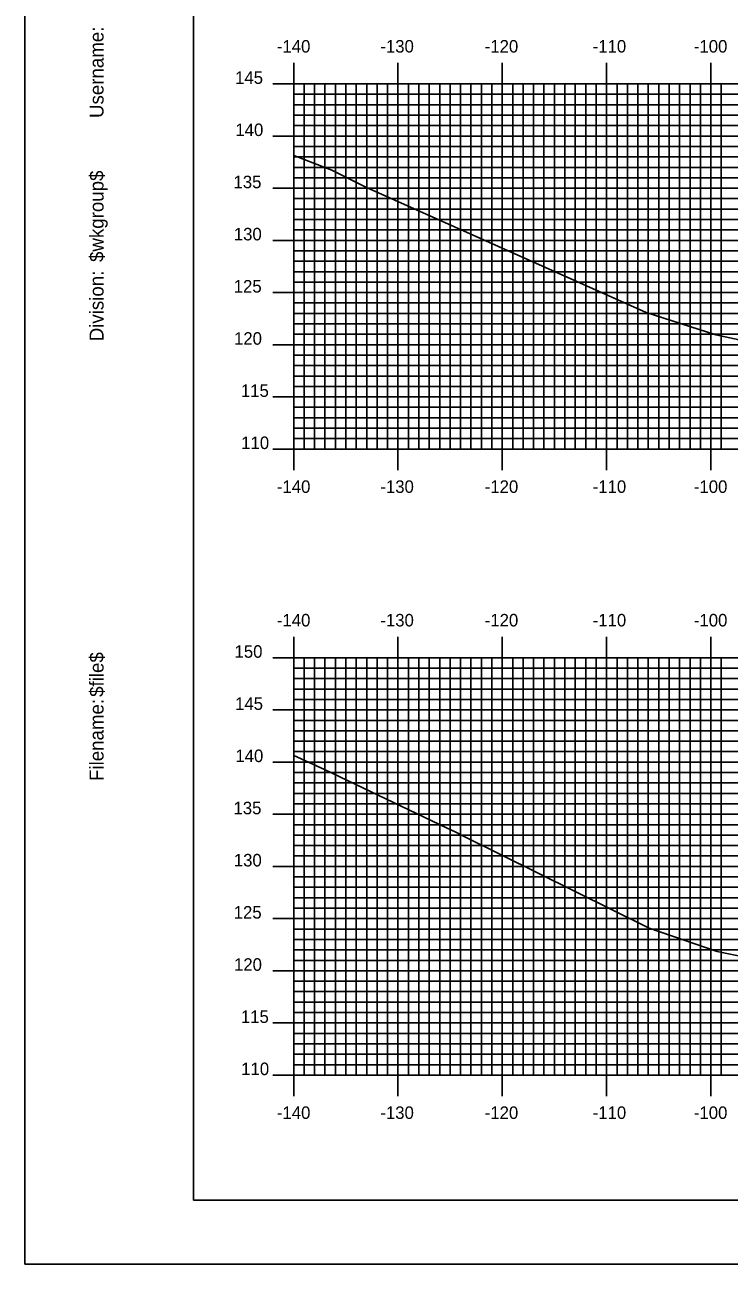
# Model space of a CAD drawing. Extents: x 853107 to 853450, y 366605 to 366825.
# Drawn here: x 853106.7 to 853174.3, y 366604.9 to 366723.7 of the extents above; entities that cross this region are included whole.
import ezdxf

# ---------------------------------------------------------------- set-up
doc = ezdxf.new("R2010")
doc.units = 0
for name, color, linetype in [('BORDER', 7, 'Continuous'), ('H_V ANNOTATION', 7, 'Continuous'), ('MAJOR', 7, 'Continuous'), ('MINOR', 7, 'Continuous'), ('PLOT BOUNDARY', 7, 'Continuous'), ('S_Roadway_Centerline', 7, 'Continuous')]:
    doc.layers.add(name, color=color, linetype=linetype)

msp = doc.modelspace()

# ---------------------------------------------------------------- linework, layer by layer
at = {"layer": 'BORDER'}
msp.add_lwpolyline([(853122.9, 366611.06), (853442.9, 366611.06), (853442.9, 366821.06), (853122.9, 366821.06)], close=True, dxfattribs=at)
at = {"layer": 'MAJOR'}
for p, q in [((853132.5, 366720.06), (853132.5, 366718.06)), ((853142.5, 366720.06), (853142.5, 366718.06)), ((853152.5, 366720.06), (853152.5, 366718.06)), ((853162.5, 366720.06), (853162.5, 366718.06)), ((853172.5, 366720.06), (853172.5, 366718.06)), ((853130.5, 366718.06), (853132.5, 366718.06)), ((853132.5, 366718.06), (853412.5, 366718.06)), ((853132.5, 366683.06), (853132.5, 366718.06)), ((853132.5, 366683.06), (853132.5, 366718.06)), ((853132.5, 366718.06), (853412.5, 366718.06)), ((853142.5, 366683.06), (853142.5, 366718.06)), ((853152.5, 366683.06), (853152.5, 366718.06)), ((853162.5, 366683.06), (853162.5, 366718.06)), ((853172.5, 366683.06), (853172.5, 366718.06)), ((853130.5, 366713.06), (853132.5, 366713.06)), ((853132.5, 366713.06), (853412.5, 366713.06)), ((853130.5, 366708.06), (853132.5, 366708.06)), ((853132.5, 366708.06), (853412.5, 366708.06)), ((853130.5, 366703.06), (853132.5, 366703.06)), ((853132.5, 366703.06), (853412.5, 366703.06)), ((853130.5, 366698.06), (853132.5, 366698.06)), ((853132.5, 366698.06), (853412.5, 366698.06)), ((853130.5, 366693.06), (853132.5, 366693.06)), ((853132.5, 366693.06), (853412.5, 366693.06)), ((853130.5, 366688.06), (853132.5, 366688.06)), ((853132.5, 366688.06), (853412.5, 366688.06)), ((853130.5, 366683.06), (853132.5, 366683.06)), ((853132.5, 366683.06), (853412.5, 366683.06)), ((853132.5, 366683.06), (853412.5, 366683.06)), ((853132.5, 366681.05), (853132.5, 366683.06)), ((853142.5, 366681.05), (853142.5, 366683.06)), ((853152.5, 366681.05), (853152.5, 366683.06)), ((853162.5, 366681.05), (853162.5, 366683.06)), ((853172.5, 366681.05), (853172.5, 366683.06)), ((853132.5, 366665.06), (853132.5, 366663.06)), ((853142.5, 366665.06), (853142.5, 366663.06)), ((853152.5, 366665.06), (853152.5, 366663.06)), ((853162.5, 366665.06), (853162.5, 366663.06)), ((853172.5, 366665.06), (853172.5, 366663.06)), ((853130.5, 366663.06), (853132.5, 366663.06)), ((853132.5, 366663.06), (853412.5, 366663.06)), ((853132.5, 366623.06), (853132.5, 366663.06)), ((853132.5, 366623.06), (853132.5, 366663.06)), ((853132.5, 366663.06), (853412.5, 366663.06)), ((853142.5, 366623.06), (853142.5, 366663.06)), ((853152.5, 366623.06), (853152.5, 366663.06)), ((853162.5, 366623.06), (853162.5, 366663.06)), ((853172.5, 366623.06), (853172.5, 366663.06)), ((853130.5, 366658.06), (853132.5, 366658.06)), ((853132.5, 366658.06), (853412.5, 366658.06)), ((853130.5, 366653.06), (853132.5, 366653.06)), ((853132.5, 366653.06), (853412.5, 366653.06)), ((853130.5, 366648.06), (853132.5, 366648.06)), ((853132.5, 366648.06), (853412.5, 366648.06)), ((853130.5, 366643.06), (853132.5, 366643.06)), ((853132.5, 366643.06), (853412.5, 366643.06)), ((853130.5, 366638.06), (853132.5, 366638.06)), ((853132.5, 366638.06), (853412.5, 366638.06)), ((853130.5, 366633.06), (853132.5, 366633.06)), ((853132.5, 366633.06), (853412.5, 366633.06)), ((853130.5, 366628.06), (853132.5, 366628.06)), ((853132.5, 366628.06), (853412.5, 366628.06)), ((853130.5, 366623.06), (853132.5, 366623.06)), ((853132.5, 366623.06), (853412.5, 366623.06)), ((853132.5, 366623.06), (853412.5, 366623.06)), ((853132.5, 366621.05), (853132.5, 366623.06)), ((853142.5, 366621.05), (853142.5, 366623.06)), ((853152.5, 366621.05), (853152.5, 366623.06)), ((853162.5, 366621.05), (853162.5, 366623.06)), ((853172.5, 366621.05), (853172.5, 366623.06))]:
    msp.add_line(p, q, dxfattribs=at)
at = {"layer": 'MINOR'}
for p, q in [((853133.5, 366683.06), (853133.5, 366718.06)), ((853134.5, 366683.06), (853134.5, 366718.06)), ((853135.5, 366683.06), (853135.5, 366718.06)), ((853136.5, 366683.06), (853136.5, 366718.06)), ((853137.5, 366683.06), (853137.5, 366718.06)), ((853138.5, 366683.06), (853138.5, 366718.06)), ((853139.5, 366683.06), (853139.5, 366718.06)), ((853140.5, 366683.06), (853140.5, 366718.06)), ((853141.5, 366683.06), (853141.5, 366718.06)), ((853143.5, 366683.06), (853143.5, 366718.06)), ((853144.5, 366683.06), (853144.5, 366718.06)), ((853145.5, 366683.06), (853145.5, 366718.06)), ((853146.5, 366683.06), (853146.5, 366718.06)), ((853147.5, 366683.06), (853147.5, 366718.06)), ((853148.5, 366683.06), (853148.5, 366718.06)), ((853149.5, 366683.06), (853149.5, 366718.06)), ((853150.5, 366683.06), (853150.5, 366718.06)), ((853151.5, 366683.06), (853151.5, 366718.06)), ((853153.5, 366683.06), (853153.5, 366718.06)), ((853154.5, 366683.06), (853154.5, 366718.06)), ((853155.5, 366683.06), (853155.5, 366718.06)), ((853156.5, 366683.06), (853156.5, 366718.06)), ((853157.5, 366683.06), (853157.5, 366718.06)), ((853158.5, 366683.06), (853158.5, 366718.06)), ((853159.5, 366683.06), (853159.5, 366718.06)), ((853160.5, 366683.06), (853160.5, 366718.06)), ((853161.5, 366683.06), (853161.5, 366718.06)), ((853163.5, 366683.06), (853163.5, 366718.06)), ((853164.5, 366683.06), (853164.5, 366718.06)), ((853165.5, 366683.06), (853165.5, 366718.06)), ((853166.5, 366683.06), (853166.5, 366718.06)), ((853167.5, 366683.06), (853167.5, 366718.06)), ((853168.5, 366683.06), (853168.5, 366718.06)), ((853169.5, 366683.06), (853169.5, 366718.06)), ((853170.5, 366683.06), (853170.5, 366718.06)), ((853171.5, 366683.06), (853171.5, 366718.06)), ((853173.5, 366683.06), (853173.5, 366718.06)), ((853132.5, 366717.06), (853412.5, 366717.06)), ((853132.5, 366717.06), (853134.51, 366717.06)), ((853132.5, 366716.06), (853412.5, 366716.06)), ((853132.5, 366716.06), (853134.51, 366716.06)), ((853132.5, 366715.06), (853412.5, 366715.06)), ((853132.5, 366715.06), (853134.51, 366715.06)), ((853132.5, 366714.06), (853412.5, 366714.06)), ((853132.5, 366714.06), (853134.51, 366714.06)), ((853132.5, 366712.06), (853412.5, 366712.06)), ((853132.5, 366712.06), (853134.51, 366712.06)), ((853132.5, 366711.06), (853412.5, 366711.06)), ((853132.5, 366711.06), (853134.51, 366711.06)), ((853132.5, 366710.06), (853412.5, 366710.06)), ((853132.5, 366710.06), (853134.51, 366710.06)), ((853132.5, 366709.06), (853412.5, 366709.06)), ((853132.5, 366709.06), (853134.51, 366709.06)), ((853132.5, 366707.06), (853412.5, 366707.06)), ((853132.5, 366707.06), (853134.51, 366707.06)), ((853132.5, 366706.06), (853412.5, 366706.06)), ((853132.5, 366706.06), (853134.51, 366706.06)), ((853132.5, 366705.06), (853412.5, 366705.06)), ((853132.5, 366705.06), (853134.51, 366705.06)), ((853132.5, 366704.06), (853412.5, 366704.06)), ((853132.5, 366704.06), (853134.51, 366704.06)), ((853132.5, 366702.06), (853412.5, 366702.06)), ((853132.5, 366702.06), (853134.51, 366702.06)), ((853132.5, 366701.06), (853412.5, 366701.06)), ((853132.5, 366701.06), (853134.51, 366701.06)), ((853132.5, 366700.06), (853412.5, 366700.06)), ((853132.5, 366700.06), (853134.51, 366700.06)), ((853132.5, 366699.06), (853412.5, 366699.06)), ((853132.5, 366699.06), (853134.51, 366699.06)), ((853132.5, 366697.06), (853412.5, 366697.06)), ((853132.5, 366697.06), (853134.51, 366697.06)), ((853132.5, 366696.06), (853412.5, 366696.06)), ((853132.5, 366696.06), (853134.51, 366696.06)), ((853132.5, 366695.06), (853412.5, 366695.06)), ((853132.5, 366695.06), (853134.51, 366695.06)), ((853132.5, 366694.06), (853412.5, 366694.06)), ((853132.5, 366694.06), (853134.51, 366694.06)), ((853132.5, 366692.06), (853412.5, 366692.06)), ((853132.5, 366692.06), (853134.51, 366692.06)), ((853132.5, 366691.06), (853412.5, 366691.06)), ((853132.5, 366691.06), (853134.51, 366691.06)), ((853132.5, 366690.06), (853412.5, 366690.06)), ((853132.5, 366690.06), (853134.51, 366690.06)), ((853132.5, 366689.06), (853412.5, 366689.06)), ((853132.5, 366689.06), (853134.51, 366689.06)), ((853132.5, 366687.06), (853412.5, 366687.06)), ((853132.5, 366687.06), (853134.51, 366687.06)), ((853132.5, 366686.06), (853412.5, 366686.06)), ((853132.5, 366686.06), (853134.51, 366686.06)), ((853132.5, 366685.06), (853412.5, 366685.06)), ((853132.5, 366685.06), (853134.51, 366685.06)), ((853132.5, 366684.06), (853412.5, 366684.06)), ((853132.5, 366684.06), (853134.51, 366684.06)), ((853133.5, 366623.06), (853133.5, 366663.06)), ((853134.5, 366623.06), (853134.5, 366663.06)), ((853135.5, 366623.06), (853135.5, 366663.06)), ((853136.5, 366623.06), (853136.5, 366663.06)), ((853137.5, 366623.06), (853137.5, 366663.06)), ((853138.5, 366623.06), (853138.5, 366663.06)), ((853139.5, 366623.06), (853139.5, 366663.06)), ((853140.5, 366623.06), (853140.5, 366663.06)), ((853141.5, 366623.06), (853141.5, 366663.06)), ((853143.5, 366623.06), (853143.5, 366663.06)), ((853144.5, 366623.06), (853144.5, 366663.06)), ((853145.5, 366623.06), (853145.5, 366663.06)), ((853146.5, 366623.06), (853146.5, 366663.06)), ((853147.5, 366623.06), (853147.5, 366663.06)), ((853148.5, 366623.06), (853148.5, 366663.06)), ((853149.5, 366623.06), (853149.5, 366663.06)), ((853150.5, 366623.06), (853150.5, 366663.06)), ((853151.5, 366623.06), (853151.5, 366663.06)), ((853153.5, 366623.06), (853153.5, 366663.06)), ((853154.5, 366623.06), (853154.5, 366663.06)), ((853155.5, 366623.06), (853155.5, 366663.06)), ((853156.5, 366623.06), (853156.5, 366663.06)), ((853157.5, 366623.06), (853157.5, 366663.06)), ((853158.5, 366623.06), (853158.5, 366663.06)), ((853159.5, 366623.06), (853159.5, 366663.06)), ((853160.5, 366623.06), (853160.5, 366663.06)), ((853161.5, 366623.06), (853161.5, 366663.06)), ((853163.5, 366623.06), (853163.5, 366663.06)), ((853164.5, 366623.06), (853164.5, 366663.06)), ((853165.5, 366623.06), (853165.5, 366663.06)), ((853166.5, 366623.06), (853166.5, 366663.06)), ((853167.5, 366623.06), (853167.5, 366663.06)), ((853168.5, 366623.06), (853168.5, 366663.06)), ((853169.5, 366623.06), (853169.5, 366663.06)), ((853170.5, 366623.06), (853170.5, 366663.06)), ((853171.5, 366623.06), (853171.5, 366663.06)), ((853173.5, 366623.06), (853173.5, 366663.06)), ((853132.5, 366662.06), (853412.5, 366662.06)), ((853132.5, 366662.06), (853134.51, 366662.06)), ((853132.5, 366661.06), (853412.5, 366661.06)), ((853132.5, 366661.06), (853134.51, 366661.06)), ((853132.5, 366660.06), (853412.5, 366660.06)), ((853132.5, 366660.06), (853134.51, 366660.06)), ((853132.5, 366659.06), (853412.5, 366659.06)), ((853132.5, 366659.06), (853134.51, 366659.06)), ((853132.5, 366657.06), (853412.5, 366657.06)), ((853132.5, 366657.06), (853134.51, 366657.06)), ((853132.5, 366656.06), (853412.5, 366656.06)), ((853132.5, 366656.06), (853134.51, 366656.06)), ((853132.5, 366655.06), (853412.5, 366655.06)), ((853132.5, 366655.06), (853134.51, 366655.06)), ((853132.5, 366654.06), (853412.5, 366654.06)), ((853132.5, 366654.06), (853134.51, 366654.06)), ((853132.5, 366652.06), (853412.5, 366652.06)), ((853132.5, 366652.06), (853134.51, 366652.06)), ((853132.5, 366651.06), (853412.5, 366651.06)), ((853132.5, 366651.06), (853134.51, 366651.06)), ((853132.5, 366650.06), (853412.5, 366650.06)), ((853132.5, 366650.06), (853134.51, 366650.06)), ((853132.5, 366649.06), (853412.5, 366649.06)), ((853132.5, 366649.06), (853134.51, 366649.06)), ((853132.5, 366647.06), (853412.5, 366647.06)), ((853132.5, 366647.06), (853134.51, 366647.06)), ((853132.5, 366646.06), (853412.5, 366646.06)), ((853132.5, 366646.06), (853134.51, 366646.06)), ((853132.5, 366645.06), (853412.5, 366645.06)), ((853132.5, 366645.06), (853134.51, 366645.06)), ((853132.5, 366644.06), (853412.5, 366644.06)), ((853132.5, 366644.06), (853134.51, 366644.06)), ((853132.5, 366642.06), (853412.5, 366642.06)), ((853132.5, 366642.06), (853134.51, 366642.06)), ((853132.5, 366641.06), (853412.5, 366641.06)), ((853132.5, 366641.06), (853134.51, 366641.06)), ((853132.5, 366640.06), (853412.5, 366640.06)), ((853132.5, 366640.06), (853134.51, 366640.06)), ((853132.5, 366639.06), (853412.5, 366639.06)), ((853132.5, 366639.06), (853134.51, 366639.06)), ((853132.5, 366637.06), (853412.5, 366637.06)), ((853132.5, 366637.06), (853134.51, 366637.06)), ((853132.5, 366636.06), (853412.5, 366636.06)), ((853132.5, 366636.06), (853134.51, 366636.06)), ((853132.5, 366635.06), (853412.5, 366635.06)), ((853132.5, 366635.06), (853134.51, 366635.06)), ((853132.5, 366634.06), (853412.5, 366634.06)), ((853132.5, 366634.06), (853134.51, 366634.06)), ((853132.5, 366632.06), (853412.5, 366632.06)), ((853132.5, 366632.06), (853134.51, 366632.06)), ((853132.5, 366631.06), (853412.5, 366631.06)), ((853132.5, 366631.06), (853134.51, 366631.06)), ((853132.5, 366630.06), (853412.5, 366630.06)), ((853132.5, 366630.06), (853134.51, 366630.06)), ((853132.5, 366629.06), (853412.5, 366629.06)), ((853132.5, 366629.06), (853134.51, 366629.06)), ((853132.5, 366627.06), (853412.5, 366627.06)), ((853132.5, 366627.06), (853134.51, 366627.06)), ((853132.5, 366626.06), (853412.5, 366626.06)), ((853132.5, 366626.06), (853134.51, 366626.06)), ((853132.5, 366625.06), (853412.5, 366625.06)), ((853132.5, 366625.06), (853134.51, 366625.06)), ((853132.5, 366624.06), (853412.5, 366624.06)), ((853132.5, 366624.06), (853134.51, 366624.06))]:
    msp.add_line(p, q, dxfattribs=at)
at = {"layer": 'PLOT BOUNDARY'}
msp.add_lwpolyline([(853106.72, 366604.94), (853446.72, 366604.94), (853446.72, 366824.94), (853106.72, 366824.94)], close=True, dxfattribs=at)
at = {"layer": 'S_Roadway_Centerline'}
for points in [[(853132.5, 366711.19), (853136.15, 366709.79), (853139.47, 366708.14), (853166.29, 366696.15), (853172.98, 366694.01), (853177.28, 366693.08), (853179.23, 366692.99), (853189.7, 366695.2), (853194.1, 366696.11), (853200.88, 366696.93), (853201.43, 366696.92), (853210.25, 366697.23), (853213.84, 366697.36), (853216.32, 366697.44), (853216.51, 366697.43), (853219.19, 366697.5), (853223.14, 366697.57), (853228.77, 366697.71), (853232.64, 366697.78), (853240.8, 366697.96)], [(853132.5, 366653.68), (853135.46, 366652.34), (853147.22, 366646.73), (853147.98, 366646.36), (853148.84, 366645.94), (853166.58, 366637.15), (853173.1, 366634.9), (853180.75, 366633.34), (853182.02, 366633.1), (853183.71, 366633.28), (853193.39, 366635.16), (853200.79, 366636.45), (853204.64, 366636.88), (853205.13, 366636.82), (853210.17, 366637.08), (853219.65, 366637.54), (853220.08, 366637.56), (853220.74, 366637.58), (853223.92, 366637.67), (853230.24, 366637.86), (853241.74, 366638.1)]]:
    msp.add_lwpolyline(points, dxfattribs=at)

# ---------------------------------------------------------------- texts
at = {"layer": 'BORDER'}
for s, p in [('Username:', (853114.27, 366714.79)), ('$wkgroup$', (853114.27, 366700.99)), ('Division:', (853114.27, 366693.39)), ('$file$', (853114.27, 366659.31)), ('Filename:', (853114.27, 366651.25))]:
    msp.add_text(s, height=1.339, rotation=90, dxfattribs=at).set_placement(p)
at = {"layer": 'H_V ANNOTATION'}
for s, p in [('-140', (853130.89, 366721.06)), ('-130', (853140.81, 366721.06)), ('-120', (853150.82, 366721.06)), ('-110', (853161.17, 366721.06)), ('-100', (853170.87, 366721.06)), ('145', (853126.88, 366718.06)), ('140', (853126.91, 366713.06)), ('135', (853126.73, 366708.06)), ('130', (853126.76, 366703.06)), ('125', (853126.75, 366698.06)), ('120', (853126.78, 366693.06)), ('115', (853127.44, 366688.06)), ('110', (853127.47, 366683.06)), ('-140', (853130.89, 366678.86)), ('-130', (853140.81, 366678.86)), ('-120', (853150.82, 366678.86)), ('-110', (853161.17, 366678.86)), ('-100', (853170.87, 366678.86)), ('-140', (853130.89, 366666.06)), ('-130', (853140.81, 366666.06)), ('-120', (853150.82, 366666.06)), ('-110', (853161.17, 366666.06)), ('-100', (853170.87, 366666.06)), ('150', (853126.83, 366663.06)), ('145', (853126.88, 366658.06)), ('140', (853126.91, 366653.06)), ('135', (853126.73, 366648.06)), ('130', (853126.76, 366643.06)), ('125', (853126.75, 366638.06)), ('120', (853126.78, 366633.06)), ('115', (853127.44, 366628.06)), ('110', (853127.47, 366623.06)), ('-140', (853130.89, 366618.86)), ('-130', (853140.81, 366618.86)), ('-120', (853150.82, 366618.86)), ('-110', (853161.17, 366618.86)), ('-100', (853170.87, 366618.86))]:
    msp.add_text(s, height=1.2, dxfattribs=at).set_placement(p)
at = {"layer": 'MAJOR'}
for p in [(853132.49, 366683.06), (853132.49, 366623.06)]:
    msp.add_text('-', height=0.012, dxfattribs=at).set_placement(p)

doc.saveas('drawing.dxf')
